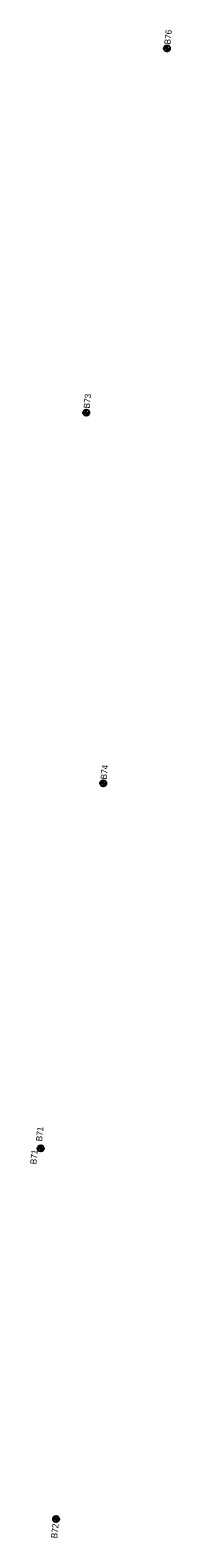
# Model space of a CAD drawing. Extents: x 331323 to 388339, y 121519 to 205315.
# Drawn here: x 359709 to 359939, y 169419 to 171874 of the extents above; entities that cross this region are included whole.
import ezdxf

# ---------------------------------------------------------------- set-up
doc = ezdxf.new("R2010")
doc.units = 0
for name, color, linetype in [('E_SOIL_BORE1 [KAPUR_CADDS_LEVELS]', 7, 'Continuous'), ('E_SOIL_BORE2 [KAPUR_CADDS_LEVELS]', 7, 'Continuous'), ('P_MARK', 7, 'Continuous')]:
    doc.layers.add(name, color=color, linetype=linetype)

msp = doc.modelspace()

# ---------------------------------------------------------------- linework, layer by layer
at = {"layer": 'P_MARK'}
for p, q in [((359926.5, 171844), (359936.5, 171844)), ((359931.5, 171849), (359931.5, 171839)), ((359795.3, 171250.9), (359805.3, 171250.9)), ((359800.3, 171255.9), (359800.3, 171245.9)), ((359828, 170652.5), (359828, 170642.5)), ((359823, 170647.5), (359833, 170647.5)), ((359721.4, 170053), (359731.4, 170053)), ((359726.4, 170058), (359726.4, 170048)), ((359746.5, 169449.5), (359756.5, 169449.5)), ((359751.5, 169454.5), (359751.5, 169444.5))]:
    msp.add_line(p, q, dxfattribs=at)
for centre in [(359931.5, 171844), (359800.3, 171250.9), (359828, 170647.5), (359726.4, 170053), (359751.5, 169449.5)]:
    msp.add_circle(centre, 5, dxfattribs=at)
for centre, radius, start, end in [((359931.5, 171844), 4.5, 89.9869, 179.9869), ((359931.5, 171844), 4, 89.9869, 179.9869), ((359931.5, 171844), 3.5, 89.9869, 179.9869), ((359931.5, 171844), 3, 89.9869, 179.9869), ((359931.5, 171844), 2.5, 89.9869, 179.9869), ((359931.5, 171844), 2, 89.9869, 179.9869), ((359931.5, 171844), 1.5, 89.9869, 179.9869), ((359931.5, 171844), 1, 89.9869, 179.9869), ((359931.5, 171844), 0.5, 89.9869, 179.9869), ((359931.5, 171844), 4.5, 269.9869, 359.9869), ((359931.5, 171844), 4, 269.9869, 359.9869), ((359931.5, 171844), 3.5, 269.9869, 359.9869), ((359931.5, 171844), 3, 269.9869, 359.9869), ((359931.5, 171844), 2.5, 269.9869, 359.9869), ((359931.5, 171844), 2, 269.9869, 359.9869), ((359931.5, 171844), 1.5, 269.9869, 359.9869), ((359931.5, 171844), 1, 269.9869, 359.9869), ((359931.5, 171844), 0.5, 269.9869, 359.9869), ((359800.3, 171250.9), 4.5, 89.9869, 179.9869), ((359800.3, 171250.9), 4, 89.9869, 179.9869), ((359800.3, 171250.9), 3.5, 89.9869, 179.9869), ((359800.3, 171250.9), 3, 89.9869, 179.9869), ((359800.3, 171250.9), 2.5, 89.9869, 179.9869), ((359800.3, 171250.9), 2, 89.9869, 179.9869), ((359800.3, 171250.9), 1.5, 89.9869, 179.9869), ((359800.3, 171250.9), 1, 89.9869, 179.9869), ((359800.3, 171250.9), 0.5, 89.9869, 179.9869), ((359800.3, 171250.9), 4.5, 269.9869, 359.9869), ((359800.3, 171250.9), 4, 269.9869, 359.9869), ((359800.3, 171250.9), 3.5, 269.9869, 359.9869), ((359800.3, 171250.9), 3, 269.9869, 359.9869), ((359800.3, 171250.9), 2.5, 269.9869, 359.9869), ((359800.3, 171250.9), 2, 269.9869, 359.9869), ((359800.3, 171250.9), 1.5, 269.9869, 359.9869), ((359800.3, 171250.9), 1, 269.9869, 359.9869), ((359800.3, 171250.9), 0.5, 269.9869, 359.9869), ((359828, 170647.5), 4.5, 89.9869, 179.9869), ((359828, 170647.5), 4, 89.9869, 179.9869), ((359828, 170647.5), 3.5, 89.9869, 179.9869), ((359828, 170647.5), 3, 89.9869, 179.9869), ((359828, 170647.5), 2.5, 89.9869, 179.9869), ((359828, 170647.5), 2, 89.9869, 179.9869), ((359828, 170647.5), 1.5, 89.9869, 179.9869), ((359828, 170647.5), 1, 89.9869, 179.9869), ((359828, 170647.5), 0.5, 89.9869, 179.9869), ((359828, 170647.5), 4.5, 269.9869, 359.9869), ((359828, 170647.5), 4, 269.9869, 359.9869), ((359828, 170647.5), 3.5, 269.9869, 359.9869), ((359828, 170647.5), 3, 269.9869, 359.9869), ((359828, 170647.5), 2.5, 269.9869, 359.9869), ((359828, 170647.5), 2, 269.9869, 359.9869), ((359828, 170647.5), 1.5, 269.9869, 359.9869), ((359828, 170647.5), 1, 269.9869, 359.9869), ((359828, 170647.5), 0.5, 269.9869, 359.9869), ((359726.4, 170053), 4.5, 89.9869, 179.9869), ((359726.4, 170053), 4, 89.9869, 179.9869), ((359726.4, 170053), 3.5, 89.9869, 179.9869), ((359726.4, 170053), 3, 89.9869, 179.9869), ((359726.4, 170053), 2.5, 89.9869, 179.9869), ((359726.4, 170053), 2, 89.9869, 179.9869), ((359726.4, 170053), 1.5, 89.9869, 179.9869), ((359726.4, 170053), 1, 89.9869, 179.9869), ((359726.4, 170053), 0.5, 89.9869, 179.9869), ((359726.4, 170053), 4.5, 269.9869, 359.9869), ((359726.4, 170053), 4, 269.9869, 359.9869), ((359726.4, 170053), 3.5, 269.9869, 359.9869), ((359726.4, 170053), 3, 269.9869, 359.9869), ((359726.4, 170053), 2.5, 269.9869, 359.9869), ((359726.4, 170053), 2, 269.9869, 359.9869), ((359726.4, 170053), 1.5, 269.9869, 359.9869), ((359726.4, 170053), 1, 269.9869, 359.9869), ((359726.4, 170053), 0.5, 269.9869, 359.9869), ((359751.5, 169449.5), 4.5, 89.9869, 179.9869), ((359751.5, 169449.5), 4, 89.9869, 179.9869), ((359751.5, 169449.5), 3.5, 89.9869, 179.9869), ((359751.5, 169449.5), 3, 89.9869, 179.9869), ((359751.5, 169449.5), 2.5, 89.9869, 179.9869), ((359751.5, 169449.5), 2, 89.9869, 179.9869), ((359751.5, 169449.5), 1.5, 89.9869, 179.9869), ((359751.5, 169449.5), 1, 89.9869, 179.9869), ((359751.5, 169449.5), 0.5, 89.9869, 179.9869), ((359751.5, 169449.5), 4.5, 269.9869, 359.9869), ((359751.5, 169449.5), 4, 269.9869, 359.9869), ((359751.5, 169449.5), 3.5, 269.9869, 359.9869), ((359751.5, 169449.5), 3, 269.9869, 359.9869), ((359751.5, 169449.5), 2.5, 269.9869, 359.9869), ((359751.5, 169449.5), 2, 269.9869, 359.9869), ((359751.5, 169449.5), 1.5, 269.9869, 359.9869), ((359751.5, 169449.5), 1, 269.9869, 359.9869), ((359751.5, 169449.5), 0.5, 269.9869, 359.9869)]:
    msp.add_arc(centre, radius, start, end, dxfattribs=at)

# ---------------------------------------------------------------- texts
at = {"layer": 'E_SOIL_BORE1 [KAPUR_CADDS_LEVELS]'}
for s, p in [('B73', (359806, 171257.5)), ('B74', (359833.6, 170653.4)), ('B71', (359728.5, 170064.1))]:
    msp.add_text(s, height=10, rotation=84.1728, dxfattribs=at).set_placement(p)
at = {"layer": 'E_SOIL_BORE2 [KAPUR_CADDS_LEVELS]'}
for s, p in [('B76', (359937.1, 171850.2)), ('B71', (359719.2, 170026.7)), ('B72', (359753.1, 169417.7))]:
    msp.add_text(s, height=10, rotation=84.1728, dxfattribs=at).set_placement(p)

doc.saveas('drawing.dxf')
